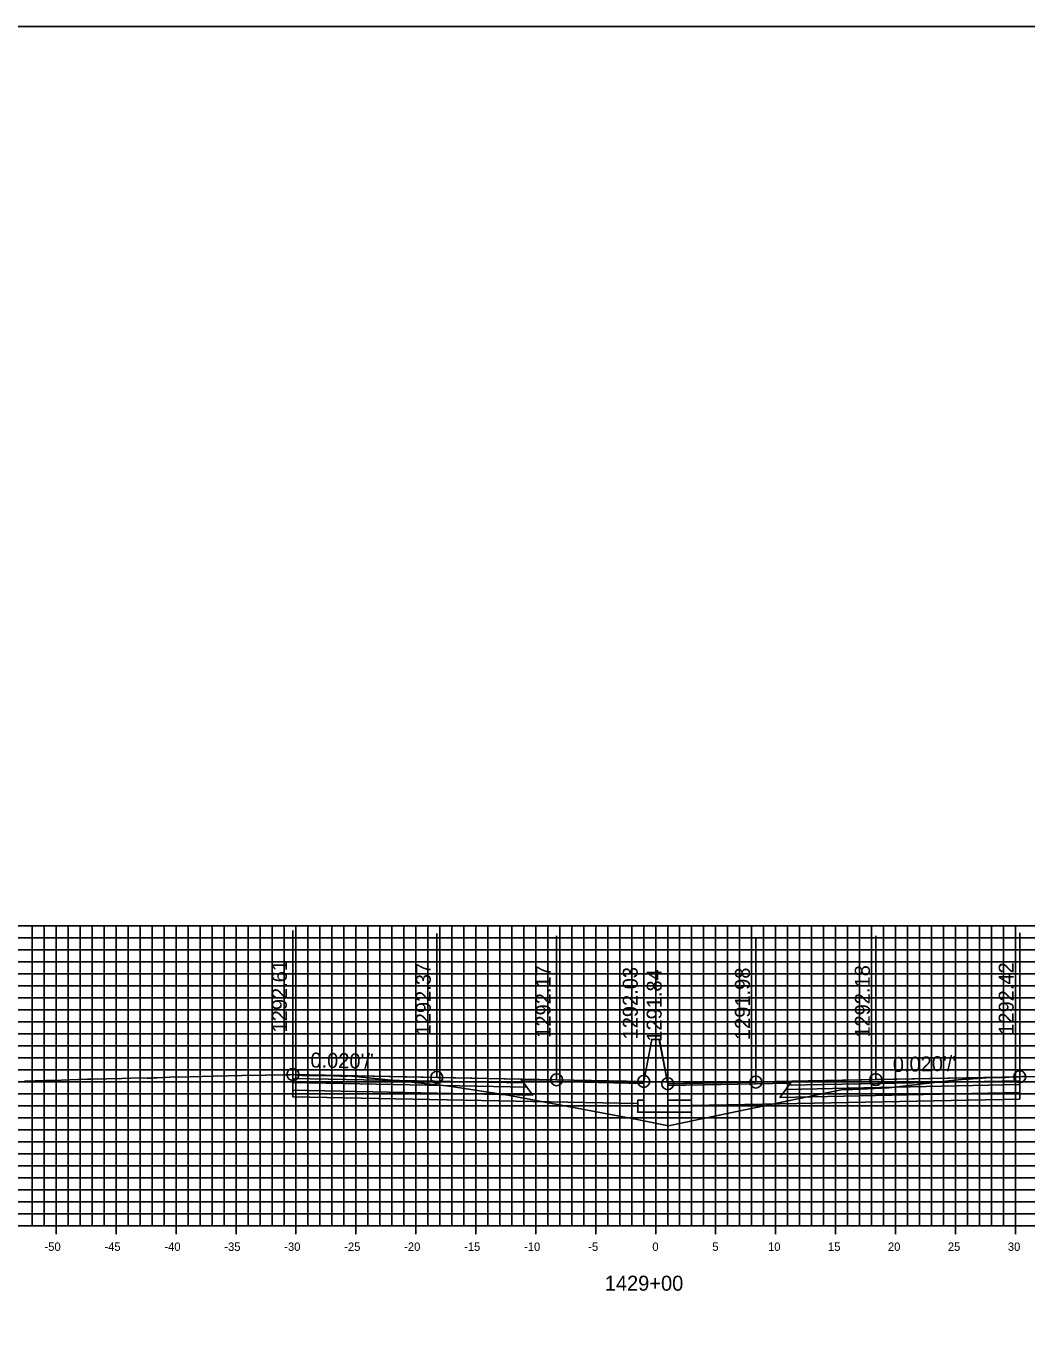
# Model space of a CAD drawing. Extents: x 674939 to 678919, y 750652 to 765176.
# Drawn here: x 678696 to 678779.5, y 758162.6 to 758272.6 of the extents above; entities that cross this region are included whole.
import ezdxf

# ---------------------------------------------------------------- set-up
doc = ezdxf.new("R2010")
doc.units = 0
for name, color, linetype in [('R_Alt Surface', 7, 'Continuous'), ('R_Axis', 7, 'Continuous'), ('R_Axis Annot', 7, 'Continuous'), ('R_Exist Surface', 7, 'Continuous'), ('R_Fin Surface', 7, 'Continuous'), ('R_Grid', 7, 'Continuous'), ('R_No Plot', 7, 'Continuous'), ('R_Proposed Road', 7, 'Continuous'), ('R_Xsect Elev', 7, 'Continuous'), ('R_Xsect Slope', 7, 'Continuous')]:
    doc.layers.add(name, color=color, linetype=linetype)

msp = doc.modelspace()

# ---------------------------------------------------------------- linework, layer by layer
for points in [[(678748.2, 758188.08), (678747.53, 758184.58)], [(678748.86, 758187.89), (678748.86, 758188.08), (678748.2, 758188.08), (678748.2, 758188.08)], [(678748.86, 758187.89), (678749.53, 758184.39)]]:
    msp.add_lwpolyline(points)
at = {"layer": 'R_Alt Surface'}
for points in [[(678718.27, 758184.83), (678718.27, 758184.5), (678737.77, 758184.11), (678737.52, 758184.45)], [(678718.27, 758184.5), (678718.27, 758183.84), (678738.27, 758183.44), (678737.77, 758184.11)], [(678778.89, 758184.31), (678778.89, 758183.65), (678758.89, 758183.25), (678759.39, 758183.92)], [(678778.89, 758184.64), (678778.89, 758184.31), (678759.39, 758183.92), (678759.64, 758184.26)]]:
    msp.add_lwpolyline(points, close=True, dxfattribs=at)
for points in [[(678718.27, 758183.84), (678718.27, 758183.3), (678738.27, 758182.9), (678747.03, 758182.73)], [(678778.89, 758183.65), (678778.89, 758183.11), (678758.89, 758182.71), (678751.53, 758182.57)]]:
    msp.add_lwpolyline(points, dxfattribs=at)
at = {"layer": 'R_Axis'}
for p, q in [((678698.53, 758171.85), (678698.53, 758173.25)), ((678703.53, 758171.85), (678703.53, 758173.25)), ((678708.53, 758171.85), (678708.53, 758173.25)), ((678713.53, 758171.85), (678713.53, 758173.25)), ((678718.53, 758171.85), (678718.53, 758173.25)), ((678723.53, 758171.85), (678723.53, 758173.25)), ((678728.53, 758171.85), (678728.53, 758173.25)), ((678733.53, 758171.85), (678733.53, 758173.25)), ((678738.53, 758171.85), (678738.53, 758173.25)), ((678743.53, 758171.85), (678743.53, 758173.25)), ((678748.53, 758171.85), (678748.53, 758173.25)), ((678753.53, 758171.85), (678753.53, 758173.25)), ((678758.53, 758171.85), (678758.53, 758173.25)), ((678763.53, 758171.85), (678763.53, 758173.25)), ((678768.53, 758171.85), (678768.53, 758173.25)), ((678773.53, 758171.85), (678773.53, 758173.25)), ((678778.53, 758171.85), (678778.53, 758173.25)), ((678598.53, 758172.55), (678898.53, 758172.55))]:
    msp.add_line(p, q, dxfattribs=at)
at = {"layer": 'R_Exist Surface'}
msp.add_lwpolyline([(678695.89, 758184.6), (678697.66, 758184.67), (678698.28, 758184.67), (678699.64, 758184.72), (678701.13, 758184.77), (678701.51, 758184.77), (678704, 758184.83), (678705.51, 758184.87), (678706.13, 758184.86), (678706.44, 758184.86), (678706.68, 758184.87), (678706.91, 758184.89), (678708.03, 758184.93), (678709.7, 758184.97), (678711.69, 758185.02), (678714.05, 758185.07), (678716.01, 758185.11), (678717.51, 758185.13), (678718.03, 758185.14), (678718.27, 758185.16), (678718.28, 758185.17), (678718.29, 758185.17), (678718.66, 758185.11), (678719.04, 758185.08), (678719.78, 758185.07), (678720.09, 758185.07), (678720.58, 758185.07), (678721.11, 758185.07), (678722.23, 758185.03), (678722.61, 758185.01), (678722.76, 758185.03), (678722.87, 758185.04), (678726.22, 758184.71), (678728.2, 758184.53), (678729.76, 758184.36), (678731.08, 758184.22), (678732.21, 758184.05), (678736.21, 758183.44), (678746.99, 758181.4), (678749.61, 758180.88), (678753.17, 758181.62), (678764.14, 758183.91), (678764.98, 758183.92), (678767.98, 758184.04), (678773.45, 758184.68), (678774.37, 758184.78), (678774.7, 758184.78), (678774.98, 758184.8), (678776.11, 758184.87), (678777.72, 758184.92), (678778.31, 758184.95), (678778.87, 758184.97), (678778.89, 758184.97), (678779.13, 758184.99), (678779.35, 758184.98), (678780.47, 758184.96)], dxfattribs=at)
at = {"layer": 'R_Fin Surface'}
for points in [[(678718.27, 758185.16), (678730.27, 758184.92), (678737.27, 758184.78), (678740.27, 758184.72), (678747.53, 758184.58), (678748.2, 758188.08), (678748.86, 758188.08), (678749.53, 758184.39), (678756.89, 758184.53), (678759.89, 758184.59), (678766.89, 758184.73), (678778.89, 758184.97)], [(678747.53, 758184.58), (678740.27, 758184.72), (678730.27, 758184.92), (678718.27, 758185.16)], [(678778.89, 758184.97), (678766.89, 758184.73), (678756.89, 758184.53), (678749.53, 758184.39)]]:
    msp.add_lwpolyline(points, dxfattribs=at)
for points in [[(678718.27, 758185.16), (678718.27, 758184.83), (678737.52, 758184.45), (678737.27, 758184.78)], [(678778.89, 758184.97), (678778.89, 758184.64), (678759.64, 758184.26), (678759.89, 758184.59)], [(678737.27, 758184.78), (678747.53, 758184.58), (678747.54, 758184.42), (678737.39, 758184.62)], [(678759.77, 758184.43), (678749.53, 758184.23), (678749.53, 758184.39), (678759.89, 758184.59)]]:
    msp.add_lwpolyline(points, close=True, dxfattribs=at)
at = {"layer": 'R_Grid'}
for p, q in [((678598.53, 758197.55), (678898.53, 758197.55)), ((678696.53, 758172.55), (678696.53, 758197.55)), ((678697.53, 758172.55), (678697.53, 758197.55)), ((678698.53, 758172.55), (678698.53, 758197.55)), ((678699.53, 758172.55), (678699.53, 758197.55)), ((678700.53, 758172.55), (678700.53, 758197.55)), ((678701.53, 758172.55), (678701.53, 758197.55)), ((678702.53, 758172.55), (678702.53, 758197.55)), ((678703.53, 758172.55), (678703.53, 758197.55)), ((678704.53, 758172.55), (678704.53, 758197.55)), ((678705.53, 758172.55), (678705.53, 758197.55)), ((678706.53, 758172.55), (678706.53, 758197.55)), ((678707.53, 758172.55), (678707.53, 758197.55)), ((678708.53, 758172.55), (678708.53, 758197.55)), ((678709.53, 758172.55), (678709.53, 758197.55)), ((678710.53, 758172.55), (678710.53, 758197.55)), ((678711.53, 758172.55), (678711.53, 758197.55)), ((678712.53, 758172.55), (678712.53, 758197.55)), ((678713.53, 758172.55), (678713.53, 758197.55)), ((678714.53, 758172.55), (678714.53, 758197.55)), ((678715.53, 758172.55), (678715.53, 758197.55)), ((678716.53, 758172.55), (678716.53, 758197.55)), ((678717.53, 758172.55), (678717.53, 758197.55)), ((678718.53, 758172.55), (678718.53, 758197.55)), ((678719.53, 758172.55), (678719.53, 758197.55)), ((678720.53, 758172.55), (678720.53, 758197.55)), ((678721.53, 758172.55), (678721.53, 758197.55)), ((678722.53, 758172.55), (678722.53, 758197.55)), ((678723.53, 758172.55), (678723.53, 758197.55)), ((678724.53, 758172.55), (678724.53, 758197.55)), ((678725.53, 758172.55), (678725.53, 758197.55)), ((678726.53, 758172.55), (678726.53, 758197.55)), ((678727.53, 758172.55), (678727.53, 758197.55)), ((678728.53, 758172.55), (678728.53, 758197.55)), ((678729.53, 758172.55), (678729.53, 758197.55)), ((678730.53, 758172.55), (678730.53, 758197.55)), ((678731.53, 758172.55), (678731.53, 758197.55)), ((678732.53, 758172.55), (678732.53, 758197.55)), ((678733.53, 758172.55), (678733.53, 758197.55)), ((678734.53, 758172.55), (678734.53, 758197.55)), ((678735.53, 758172.55), (678735.53, 758197.55)), ((678736.53, 758172.55), (678736.53, 758197.55)), ((678737.53, 758172.55), (678737.53, 758197.55)), ((678738.53, 758172.55), (678738.53, 758197.55)), ((678739.53, 758172.55), (678739.53, 758197.55)), ((678740.53, 758172.55), (678740.53, 758197.55)), ((678741.53, 758172.55), (678741.53, 758197.55)), ((678742.53, 758172.55), (678742.53, 758197.55)), ((678743.53, 758172.55), (678743.53, 758197.55)), ((678744.53, 758172.55), (678744.53, 758197.55)), ((678745.53, 758172.55), (678745.53, 758197.55)), ((678746.53, 758172.55), (678746.53, 758197.55)), ((678747.53, 758172.55), (678747.53, 758197.55)), ((678748.53, 758172.55), (678748.53, 758197.55)), ((678749.53, 758172.55), (678749.53, 758197.55)), ((678750.53, 758172.55), (678750.53, 758197.55)), ((678751.53, 758172.55), (678751.53, 758197.55)), ((678752.53, 758172.55), (678752.53, 758197.55)), ((678753.53, 758172.55), (678753.53, 758197.55)), ((678754.53, 758172.55), (678754.53, 758197.55)), ((678755.53, 758172.55), (678755.53, 758197.55)), ((678756.53, 758172.55), (678756.53, 758197.55)), ((678757.53, 758172.55), (678757.53, 758197.55)), ((678758.53, 758172.55), (678758.53, 758197.55)), ((678759.53, 758172.55), (678759.53, 758197.55)), ((678760.53, 758172.55), (678760.53, 758197.55)), ((678761.53, 758172.55), (678761.53, 758197.55)), ((678762.53, 758172.55), (678762.53, 758197.55)), ((678763.53, 758172.55), (678763.53, 758197.55)), ((678764.53, 758172.55), (678764.53, 758197.55)), ((678765.53, 758172.55), (678765.53, 758197.55)), ((678766.53, 758172.55), (678766.53, 758197.55)), ((678767.53, 758172.55), (678767.53, 758197.55)), ((678768.53, 758172.55), (678768.53, 758197.55)), ((678769.53, 758172.55), (678769.53, 758197.55)), ((678770.53, 758172.55), (678770.53, 758197.55)), ((678771.53, 758172.55), (678771.53, 758197.55)), ((678772.53, 758172.55), (678772.53, 758197.55)), ((678773.53, 758172.55), (678773.53, 758197.55)), ((678774.53, 758172.55), (678774.53, 758197.55)), ((678775.53, 758172.55), (678775.53, 758197.55)), ((678776.53, 758172.55), (678776.53, 758197.55)), ((678777.53, 758172.55), (678777.53, 758197.55)), ((678778.53, 758172.55), (678778.53, 758197.55)), ((678598.53, 758196.55), (678898.53, 758196.55)), ((678598.53, 758195.55), (678898.53, 758195.55)), ((678598.53, 758194.55), (678898.53, 758194.55)), ((678598.53, 758193.55), (678898.53, 758193.55)), ((678598.53, 758192.55), (678898.53, 758192.55)), ((678598.53, 758191.55), (678898.53, 758191.55)), ((678598.53, 758190.55), (678898.53, 758190.55)), ((678598.53, 758189.55), (678898.53, 758189.55)), ((678598.53, 758188.55), (678898.53, 758188.55)), ((678598.53, 758187.55), (678898.53, 758187.55)), ((678598.53, 758186.55), (678898.53, 758186.55)), ((678598.53, 758185.55), (678898.53, 758185.55)), ((678598.53, 758184.55), (678898.53, 758184.55)), ((678598.53, 758183.55), (678898.53, 758183.55)), ((678598.53, 758182.55), (678898.53, 758182.55)), ((678598.53, 758181.55), (678898.53, 758181.55)), ((678598.53, 758180.55), (678898.53, 758180.55)), ((678598.53, 758179.55), (678898.53, 758179.55)), ((678598.53, 758178.55), (678898.53, 758178.55)), ((678598.53, 758177.55), (678898.53, 758177.55)), ((678598.53, 758176.55), (678898.53, 758176.55)), ((678598.53, 758175.55), (678898.53, 758175.55)), ((678598.53, 758174.55), (678898.53, 758174.55)), ((678598.53, 758173.55), (678898.53, 758173.55)), ((678598.53, 758172.55), (678898.53, 758172.55))]:
    msp.add_line(p, q, dxfattribs=at)
at = {"layer": 'R_No Plot'}
msp.add_lwpolyline([(678578.53, 758052.55), (678918.53, 758052.55), (678918.53, 758272.55), (678578.53, 758272.55)], close=True, dxfattribs=at)
for centre in [(678718.27, 758185.16), (678730.27, 758184.92), (678740.27, 758184.72), (678747.53, 758184.58), (678756.89, 758184.53), (678766.89, 758184.73), (678778.89, 758184.97), (678749.53, 758184.39)]:
    msp.add_circle(centre, 0.5, dxfattribs=at)
at = {"layer": 'R_Proposed Road'}
msp.add_lwpolyline([(678747.53, 758184.58), (678747.53, 758183.01), (678747.03, 758183.01), (678747.03, 758182.01), (678751.53, 758182.01), (678751.53, 758183.01), (678749.53, 758183.01), (678749.53, 758184.39)], dxfattribs=at)
at = {"layer": 'R_Xsect Elev'}
for p, q in [((678718.27, 758185.16), (678718.27, 758197.16)), ((678730.27, 758184.92), (678730.27, 758196.92)), ((678740.27, 758184.72), (678740.27, 758196.72)), ((678747.53, 758184.58), (678747.53, 758196.58)), ((678749.53, 758184.39), (678749.53, 758196.39)), ((678756.89, 758184.53), (678756.89, 758196.53)), ((678766.89, 758184.73), (678766.89, 758196.73)), ((678778.89, 758184.97), (678778.89, 758196.97))]:
    msp.add_line(p, q, dxfattribs=at)

# ---------------------------------------------------------------- texts
at = {"layer": 'R_Axis Annot'}
for s, height, p in [('-50', 0.7, (678697.55, 758170.45)), ('-45', 0.7, (678702.55, 758170.45)), ('-40', 0.7, (678707.55, 758170.45)), ('-35', 0.7, (678712.55, 758170.45)), ('-30', 0.7, (678717.55, 758170.45)), ('-25', 0.7, (678722.55, 758170.45)), ('-20', 0.7, (678727.55, 758170.45)), ('-15', 0.7, (678732.55, 758170.45)), ('-10', 0.7, (678737.55, 758170.45)), ('-5', 0.7, (678742.9, 758170.45)), ('0', 0.7, (678748.25, 758170.45)), ('5', 0.7, (678753.25, 758170.45)), ('10', 0.7, (678757.9, 758170.45)), ('15', 0.7, (678762.9, 758170.45)), ('20', 0.7, (678767.9, 758170.45)), ('25', 0.7, (678772.9, 758170.45)), ('30', 0.7, (678777.9, 758170.45)), ('1429+00', 1.25, (678744.28, 758167.13))]:
    msp.add_text(s, height=height, dxfattribs=at).set_placement(p)
at = {"layer": 'R_Xsect Elev'}
for s, p in [('1292.61', (678717.77, 758188.66)), ('1292.37', (678729.77, 758188.42)), ('1292.17', (678739.77, 758188.22)), ('1292.03', (678747.03, 758188.08)), ('1291.84', (678749.03, 758187.89)), ('1291.98', (678756.39, 758188.03)), ('1292.18', (678766.39, 758188.23)), ('1292.42', (678778.39, 758188.47))]:
    msp.add_text(s, height=1.25, rotation=90, dxfattribs=at).set_placement(p)
at = {"layer": 'R_Xsect Slope'}
for rotation, p in [(358.8542, (678719.72, 758185.74)), (1.1458, (678768.32, 758185.36))]:
    msp.add_text("0.020'/'", height=1.25, rotation=rotation, dxfattribs=at).set_placement(p)

doc.saveas('drawing.dxf')
